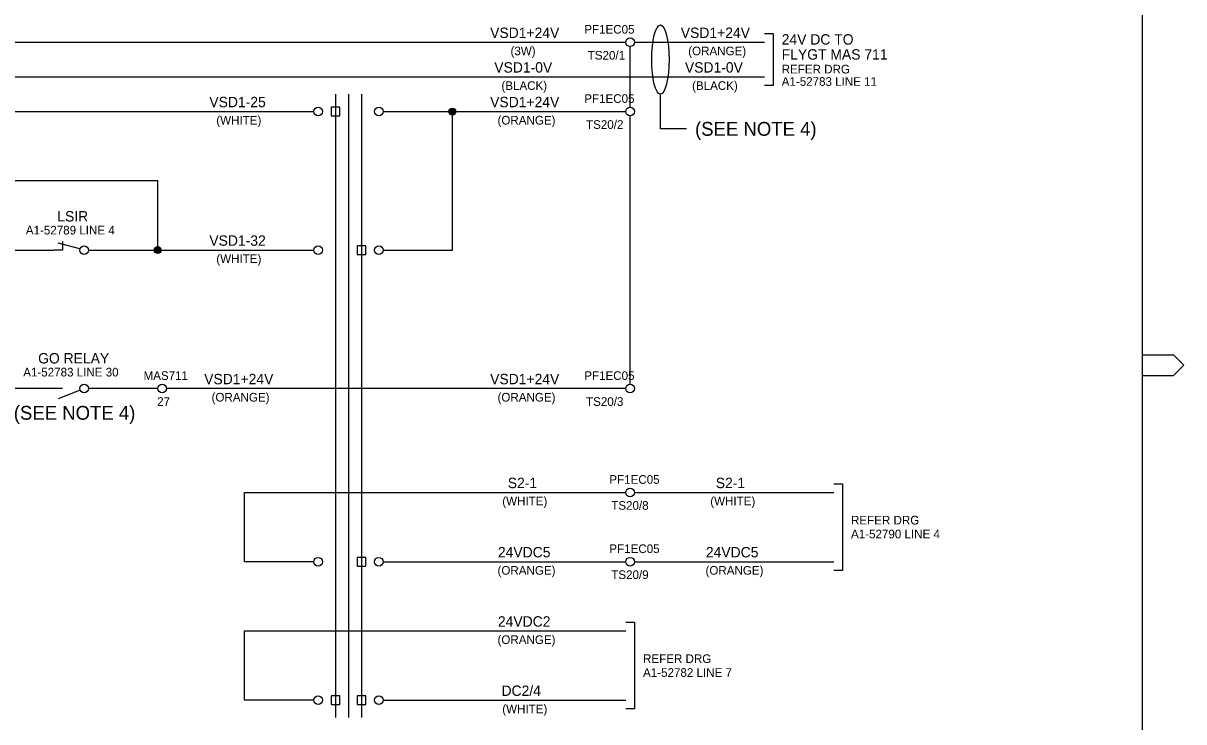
# Model space of a CAD drawing. Extents: x 0 to 841, y 0 to 594.
# Drawn here: x 506.2 to 841, y 193.8 to 395.5 of the extents above; entities that cross this region are included whole.
import ezdxf

# ---------------------------------------------------------------- set-up
doc = ezdxf.new("R2010")
doc.units = 0
for name, color, linetype in [('A1BORDER', 7, 'Continuous'), ('Level 1', 7, 'Continuous'), ('Level 10', 7, 'Continuous'), ('Level 5', 7, 'Continuous'), ('Level 6', 7, 'Continuous')]:
    doc.layers.add(name, color=color, linetype=linetype)

msp = doc.modelspace()

# ---------------------------------------------------------------- linework, layer by layer
at = {"layer": 'A1BORDER'}
for p, q in [((829, 581), (829, 15)), ((829, 299.76), (838, 299.76)), ((838, 299.76), (841, 296.76)), ((838, 293.76), (841, 296.76)), ((829, 293.76), (838, 293.76))]:
    msp.add_line(p, q, dxfattribs=at)
at = {"layer": 'Level 1'}
for p, q in [((681.25, 371.25), (681.25, 388.75)), ((596.25, 375), (596.25, 195)), ((600, 375), (600, 195)), ((603.75, 375), (603.75, 195)), ((690, 365), (690, 375)), ((630, 330), (630, 370)), ((681.25, 291.25), (681.25, 368.75)), ((697.5, 365), (690, 365)), ((545, 350), (422.5, 350)), ((545, 330), (545, 350)), ((517.5, 330), (515, 330)), ((515, 290), (495, 290)), ((517.5, 290), (515, 290)), ((545, 290), (525, 290)), ((680, 290), (547.5, 290)), ((570, 240), (570, 260)), ((590, 240), (570, 240)), ((570, 200), (570, 220)), ((590, 200), (570, 200))]:
    msp.add_line(p, q, dxfattribs=at)
for points in [[(720, 392.5), (722.5, 392.5), (722.5, 377.5), (720, 377.5)], [(740, 262.5), (742.5, 262.5), (742.5, 237.5), (740, 237.5)], [(680, 222.5), (682.5, 222.5), (682.5, 197.5), (680, 197.5)]]:
    msp.add_lwpolyline(points, dxfattribs=at)
for points in [[(595, 368.75), (597.5, 368.75), (597.5, 371.25), (595, 371.25)], [(602.5, 328.75), (605, 328.75), (605, 331.25), (602.5, 331.25)], [(602.5, 238.75), (605, 238.75), (605, 241.25), (602.5, 241.25)], [(595, 198.75), (597.5, 198.75), (597.5, 201.25), (595, 201.25)], [(602.5, 198.75), (605, 198.75), (605, 201.25), (602.5, 201.25)]]:
    msp.add_lwpolyline(points, close=True, dxfattribs=at)
msp.add_ellipse((690, 385), major_axis=(0, -10), ratio=0.25, dxfattribs=at)
at = {"layer": 'Level 10'}
for p, q in [((629, 370), (629, 370)), ((629.1, 369.56), (629.1, 370.44)), ((629.4, 369.2), (629.4, 370.8)), ((629.7, 369.05), (629.7, 370.95)), ((630, 369), (630, 370.99)), ((630.3, 369.05), (630.3, 370.95)), ((630.6, 369.2), (630.6, 370.8)), ((630.9, 369.56), (630.9, 370.44)), ((522.54, 330.32), (516.25, 332)), ((517.5, 332.5), (517.5, 330)), ((544, 330), (544, 330)), ((544.1, 329.56), (544.1, 330.44)), ((544.4, 329.2), (544.4, 330.8)), ((544.7, 329.05), (544.7, 330.95)), ((545, 329), (545, 330.99)), ((545.3, 329.05), (545.3, 330.95)), ((545.6, 329.2), (545.6, 330.8)), ((545.9, 329.56), (545.9, 330.44)), ((522.59, 289.54), (516.25, 287))]:
    msp.add_line(p, q, dxfattribs=at)
for centre, radius in [((630, 370), 1), ((523.75, 330), 1.25), ((545, 330), 1), ((523.75, 290), 1.25)]:
    msp.add_circle(centre, radius, dxfattribs=at)
at = {"layer": 'Level 5'}
for centre in [(681.25, 390), (591.25, 370), (608.75, 370), (681.25, 370), (591.25, 330), (608.75, 330), (546.25, 290), (681.25, 290), (681.25, 260), (591.25, 240), (608.75, 240), (681.25, 240), (591.25, 200), (608.75, 200)]:
    msp.add_circle(centre, 1.25, dxfattribs=at)
at = {"layer": 'Level 6'}
for p, q in [((142.5, 390), (680, 390)), ((682.5, 390), (720, 390)), ((240, 380), (720, 380)), ((240, 370), (590, 370)), ((610, 370), (680, 370)), ((465, 330), (515, 330)), ((525, 330), (590, 330)), ((610, 330), (630, 330)), ((570, 260), (680, 260)), ((682.5, 260), (740, 260)), ((610, 240), (680, 240)), ((682.5, 240), (740, 240)), ((570, 220), (680, 220)), ((610, 200), (680, 200))]:
    msp.add_line(p, q, dxfattribs=at)

# ---------------------------------------------------------------- texts
at = {"layer": 'Level 1'}
for s, height, p in [('PF1EC05', 2.5, (668.04, 392.5)), ('24V DC TO', 3, (725, 389.34)), ('FLYGT MAS 711', 3, (725, 385)), ('REFER DRG', 2.5, (725, 381)), ('A1-52783 LINE 11', 2.5, (725, 377.43)), ('PF1EC05', 2.5, (668.04, 372.5)), ('(SEE NOTE 4)', 4, (700, 363)), ('MAS711', 2.5, (540.9, 292.5)), ('PF1EC05', 2.5, (668.04, 292.5)), ('(SEE NOTE 4)', 4, (503.46, 281)), ('PF1EC05', 2.5, (675.28, 262.5)), ('REFER DRG', 2.5, (745, 250.75)), ('A1-52790 LINE 4', 2.5, (745, 246.75)), ('PF1EC05', 2.5, (675.28, 242.5)), ('REFER DRG', 2.5, (685, 210.75)), ('A1-52782 LINE 7', 2.5, (685, 206.75))]:
    msp.add_text(s, height=height, dxfattribs=at).set_placement(p)
at = {"layer": 'Level 5'}
for s, height, p in [('VSD1+24V', 3, (640.89, 391.25)), ('VSD1+24V', 3, (695.89, 391.25)), ('(3W)', 2.5, (646.76, 386.25)), ('(ORANGE)', 2.5, (698.03, 386.25)), ('TS20/1', 2.5, (669.04, 385)), ('VSD1-0V', 3, (642.08, 381.25)), ('VSD1-0V', 3, (697.08, 381.25)), ('(BLACK)', 2.5, (644.14, 376.25)), ('(BLACK)', 2.5, (699.14, 376.25)), ('VSD1-25', 3, (559.88, 371.25)), ('VSD1+24V', 3, (640.89, 371.25)), ('(WHITE)', 2.5, (561.89, 366.25)), ('(ORANGE)', 2.5, (643.02, 366.25)), ('TS20/2', 2.5, (668.55, 365)), ('LSIR', 3, (516.01, 338.25)), ('A1-52789 LINE 4', 2.5, (506.94, 334.5)), ('VSD1-32', 3, (559.88, 331.25)), ('(WHITE)', 2.5, (561.89, 326.25)), ('GO RELAY', 3, (510.48, 297.25)), ('A1-52783 LINE 30', 2.5, (506.19, 293.5)), ('VSD1+24V', 3, (558.39, 291.25)), ('VSD1+24V', 3, (640.89, 291.25)), ('(ORANGE)', 2.5, (560.52, 286.25)), ('(ORANGE)', 2.5, (643.02, 286.25)), ('27', 2.5, (544.82, 285)), ('TS20/3', 2.5, (668.55, 285)), ('S2-1', 3, (645.97, 261.25)), ('S2-1', 3, (705.97, 261.25)), ('(WHITE)', 2.5, (644.39, 256.25)), ('(WHITE)', 2.5, (704.39, 256.25)), ('TS20/8', 2.5, (675.83, 255)), ('24VDC5', 3, (643.13, 241.25)), ('24VDC5', 3, (703.13, 241.25)), ('(ORANGE)', 2.5, (643.02, 236.25)), ('(ORANGE)', 2.5, (703.02, 236.25)), ('TS20/9', 2.5, (675.83, 235)), ('24VDC2', 3, (643.13, 221.25)), ('(ORANGE)', 2.5, (643.02, 216.25)), ('DC2/4', 3, (644.17, 201.25)), ('(WHITE)', 2.5, (644.39, 196.25))]:
    msp.add_text(s, height=height, dxfattribs=at).set_placement(p)

doc.saveas('drawing.dxf')
